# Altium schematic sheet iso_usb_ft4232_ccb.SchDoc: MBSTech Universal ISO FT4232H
size A2; DrawnBy: Andrew Carpenter; Organization: MBSTech; DocumentNumber: ISO-USB-FT4323-CCB-01; Revision: Rev00a; SheetNumber: 1; SheetTotal: 1
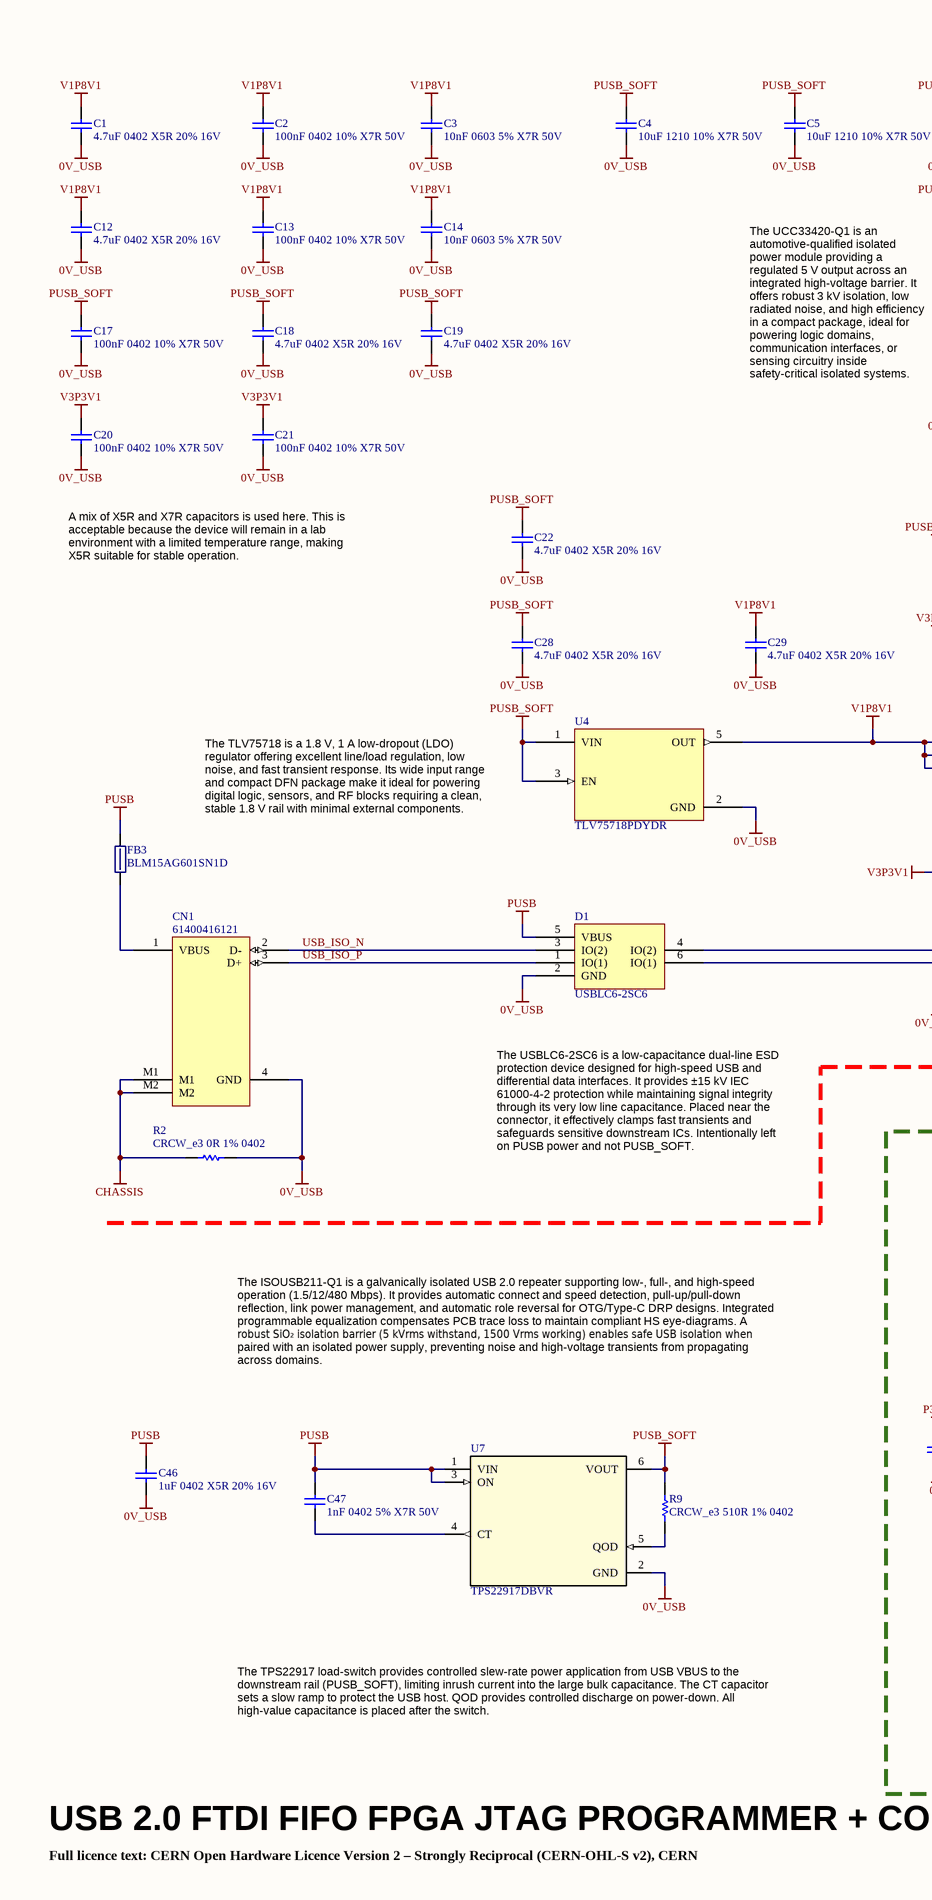
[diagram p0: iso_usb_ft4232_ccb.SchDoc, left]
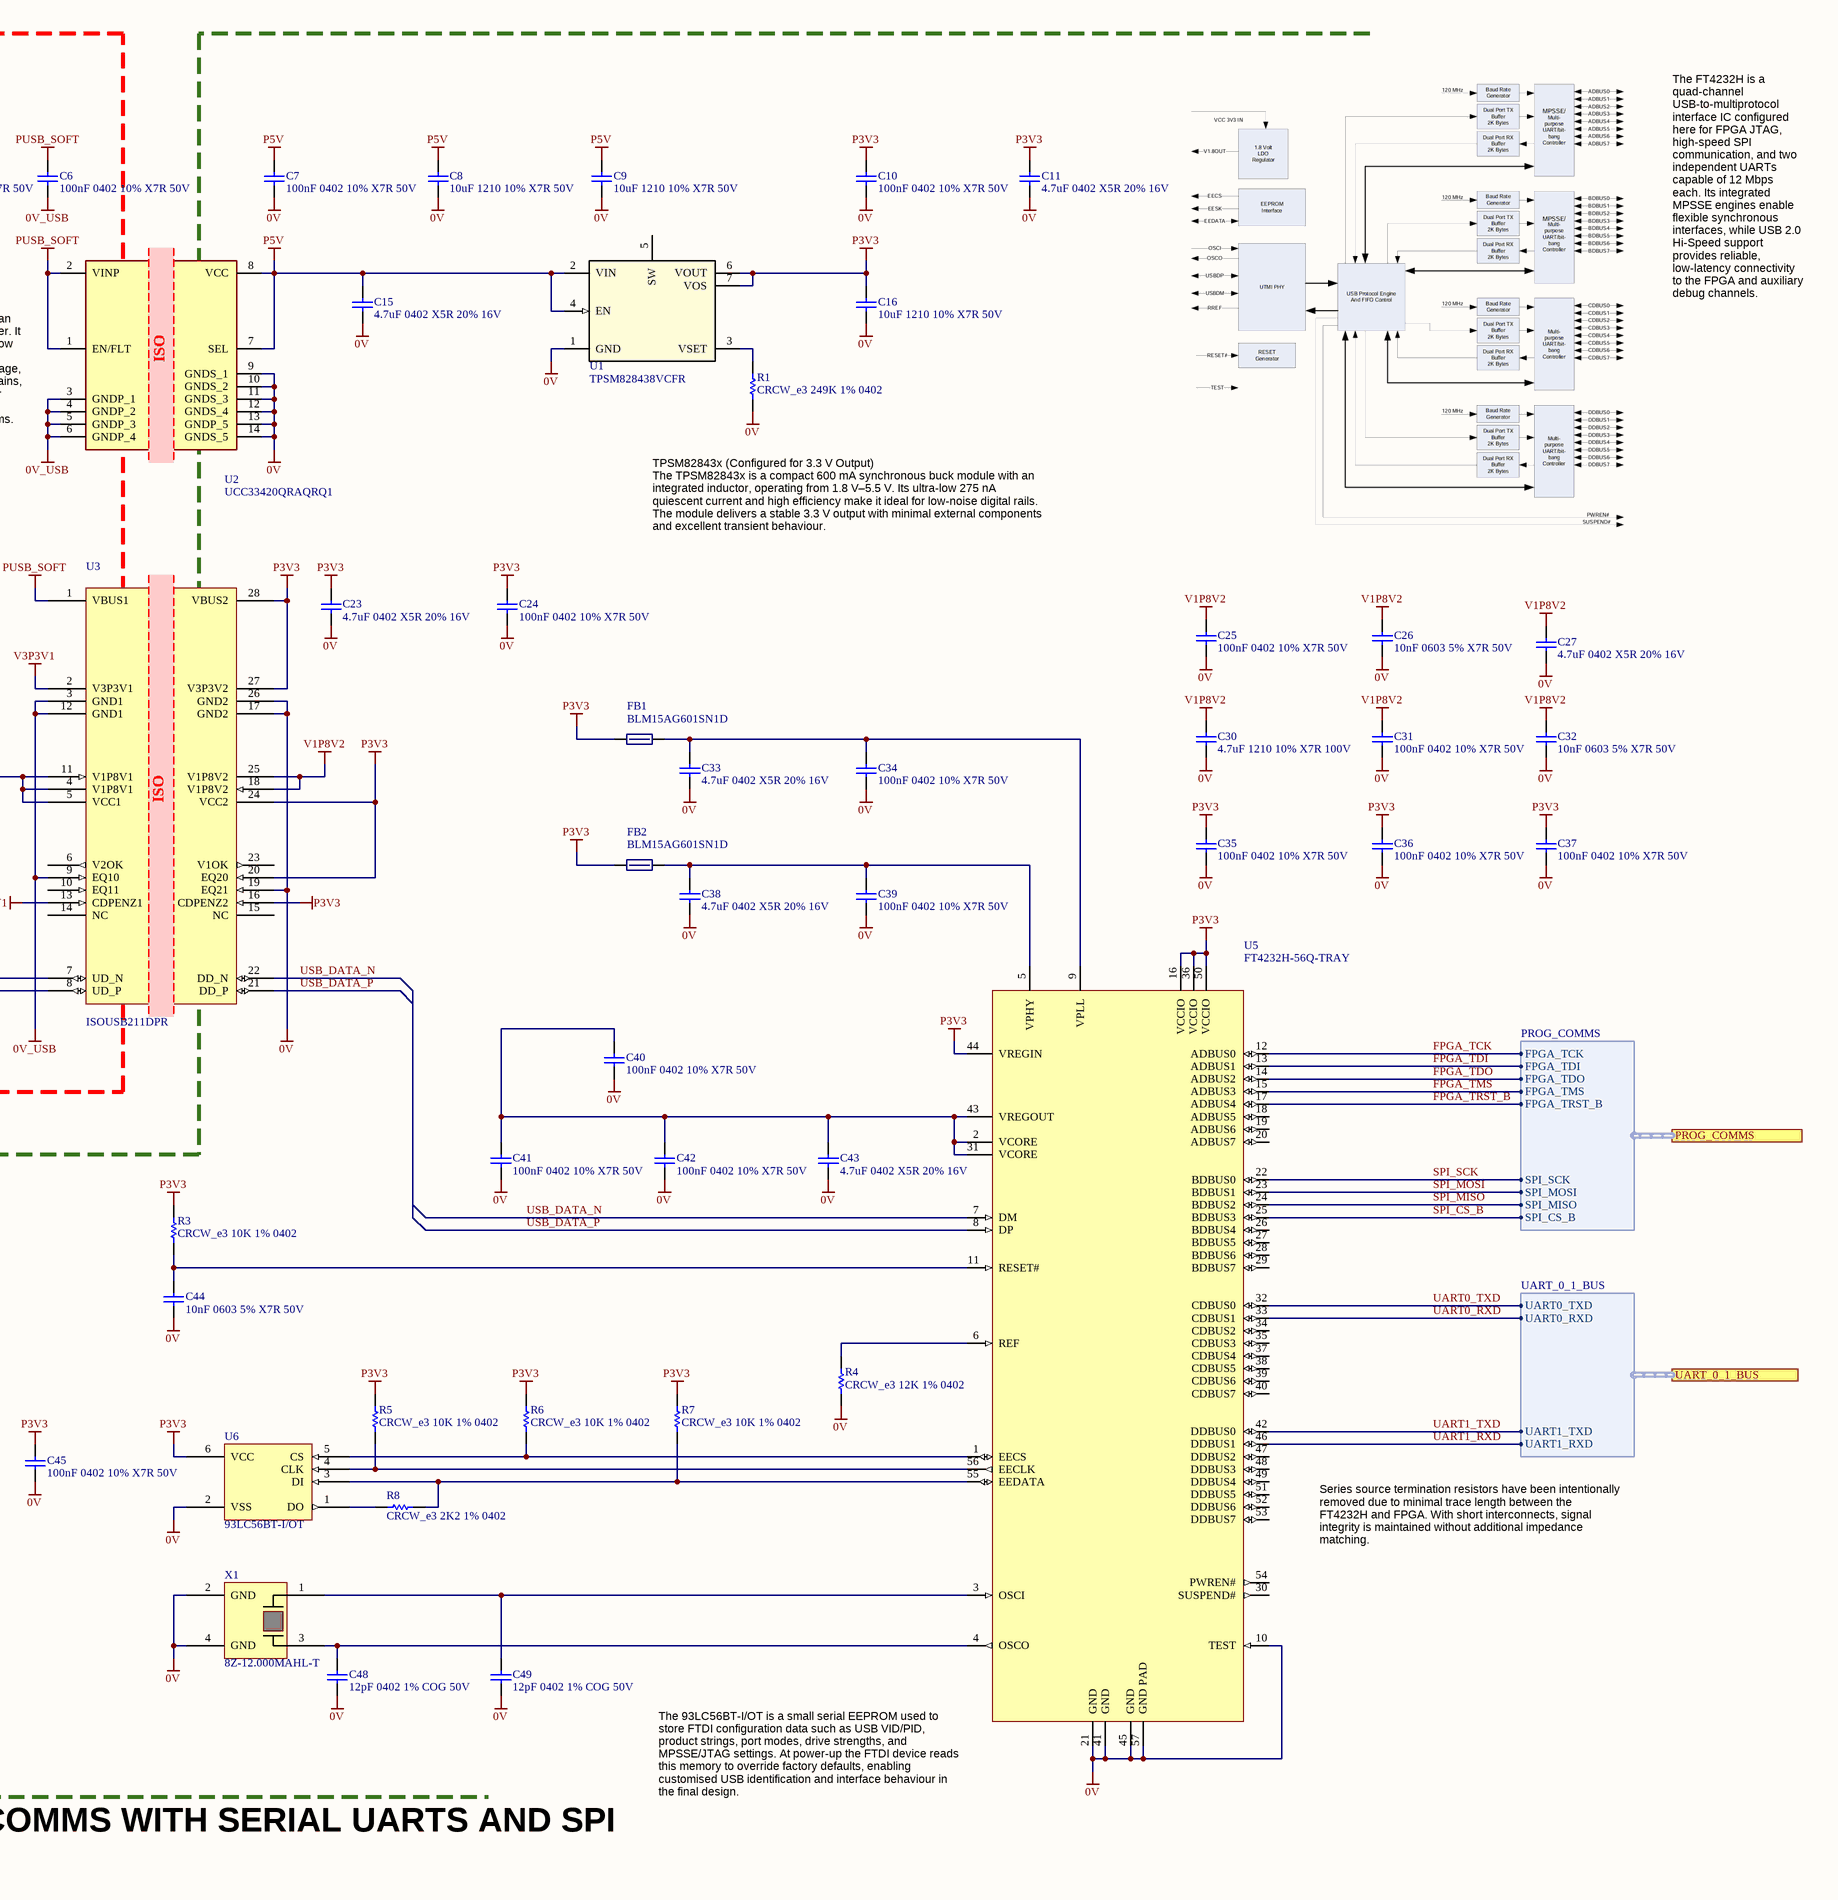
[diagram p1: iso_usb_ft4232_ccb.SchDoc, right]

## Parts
C1  4.7uF 0402 X5R 20% 16V  [CAPC100X50X56L25L-AVX0402L]
C2  100nF 0402 10% X7R 50V  [CAPC100X50X56L25L-AVX0402L]
C3  10nF 0603 5% X7R 50V  [CAPC160X81X90L35L-AVX0603L]
C4  10uF 1210 10% X7R 50V  [CAPC320X250X152L50L-AVX1210L]
C5  10uF 1210 10% X7R 50V  [CAPC320X250X152L50L-AVX1210L]
C6  100nF 0402 10% X7R 50V  [CAPC100X50X56L25L-AVX0402L]
C7  100nF 0402 10% X7R 50V  [CAPC100X50X56L25L-AVX0402L]
C8  10uF 1210 10% X7R 50V  [CAPC320X250X152L50L-AVX1210L]
C9  10uF 1210 10% X7R 50V  [CAPC320X250X152L50L-AVX1210L]
C10  100nF 0402 10% X7R 50V  [CAPC100X50X56L25L-AVX0402L]
C11  4.7uF 0402 X5R 20% 16V  [CAPC100X50X56L25L-AVX0402L]
C12  4.7uF 0402 X5R 20% 16V  [CAPC100X50X56L25L-AVX0402L]
C13  100nF 0402 10% X7R 50V  [CAPC100X50X56L25L-AVX0402L]
C14  10nF 0603 5% X7R 50V  [CAPC160X81X90L35L-AVX0603L]
C15  4.7uF 0402 X5R 20% 16V  [CAPC100X50X56L25L-AVX0402L]
C16  10uF 1210 10% X7R 50V  [CAPC320X250X152L50L-AVX1210L]
C17  100nF 0402 10% X7R 50V  [CAPC100X50X56L25L-AVX0402L]
C18  4.7uF 0402 X5R 20% 16V  [CAPC100X50X56L25L-AVX0402L]
C19  4.7uF 0402 X5R 20% 16V  [CAPC100X50X56L25L-AVX0402L]
C20  100nF 0402 10% X7R 50V  [CAPC100X50X56L25L-AVX0402L]
C21  100nF 0402 10% X7R 50V  [CAPC100X50X56L25L-AVX0402L]
C22  4.7uF 0402 X5R 20% 16V  [CAPC100X50X56L25L-AVX0402L]
C23  4.7uF 0402 X5R 20% 16V  [CAPC100X50X56L25L-AVX0402L]
C24  100nF 0402 10% X7R 50V  [CAPC100X50X56L25L-AVX0402L]
C25  100nF 0402 10% X7R 50V  [CAPC100X50X56L25L-AVX0402L]
C26  10nF 0603 5% X7R 50V  [CAPC160X81X90L35L-AVX0603L]
C27  4.7uF 0402 X5R 20% 16V  [CAPC100X50X56L25L-AVX0402L]
C28  4.7uF 0402 X5R 20% 16V  [CAPC100X50X56L25L-AVX0402L]
C29  4.7uF 0402 X5R 20% 16V  [CAPC100X50X56L25L-AVX0402L]
C30  4.7uF 1210 10% X7R 100V  [CAPC320X250X152L50L-AVX1210L]
C31  100nF 0402 10% X7R 50V  [CAPC100X50X56L25L-AVX0402L]
C32  10nF 0603 5% X7R 50V  [CAPC160X81X90L35L-AVX0603L]
C33  4.7uF 0402 X5R 20% 16V  [CAPC100X50X56L25L-AVX0402L]
C34  100nF 0402 10% X7R 50V  [CAPC100X50X56L25L-AVX0402L]
C35  100nF 0402 10% X7R 50V  [CAPC100X50X56L25L-AVX0402L]
C36  100nF 0402 10% X7R 50V  [CAPC100X50X56L25L-AVX0402L]
C37  100nF 0402 10% X7R 50V  [CAPC100X50X56L25L-AVX0402L]
C38  4.7uF 0402 X5R 20% 16V  [CAPC100X50X56L25L-AVX0402L]
C39  100nF 0402 10% X7R 50V  [CAPC100X50X56L25L-AVX0402L]
C40  100nF 0402 10% X7R 50V  [CAPC100X50X56L25L-AVX0402L]
C41  100nF 0402 10% X7R 50V  [CAPC100X50X56L25L-AVX0402L]
C42  100nF 0402 10% X7R 50V  [CAPC100X50X56L25L-AVX0402L]
C43  4.7uF 0402 X5R 20% 16V  [CAPC100X50X56L25L-AVX0402L]
C44  10nF 0603 5% X7R 50V  [CAPC160X81X90L35L-AVX0603L]
C45  100nF 0402 10% X7R 50V  [CAPC100X50X56L25L-AVX0402L]
C46  1uF 0402 X5R 20% 16V  [CAPC100X50X56L25L-AVX0402L]
C47  1nF 0402 5% X7R 50V  [CAPC100X50X56L25L-AVX0402L]
C48  12pF 0402 1% COG 50V  [CAPC100X50X56L25L-AVX0402L]
C49  12pF 0402 1% COG 50V  [CAPC100X50X56L25L-AVX0402L]
CN1  61400416121  [61400416121]
D1  USBLC6-2SC6  [SOT23-6L]
FB1  BLM15AG601SN1D  [BEADC100X50X55L25-FB0402L]
FB2  BLM15AG601SN1D  [BEADC100X50X55L25-FB0402L]
FB3  BLM15AG601SN1D  [BEADC100X50X55L25-FB0402L]
R1  CRCW_e3 249K 1% 0402  [RESC100X50X40L25-CRCW0402L]
R2  CRCW_e3 0R 1% 0402  [RESC100X50X40L25-CRCW0402L]
R3  CRCW_e3 10K 1% 0402  [RESC100X50X40L25-CRCW0402L]
R4  CRCW_e3 12K 1% 0402  [RESC100X50X40L25-CRCW0402L]
R5  CRCW_e3 10K 1% 0402  [RESC100X50X40L25-CRCW0402L]
R6  CRCW_e3 10K 1% 0402  [RESC100X50X40L25-CRCW0402L]
R7  CRCW_e3 10K 1% 0402  [RESC100X50X40L25-CRCW0402L]
R8  CRCW_e3 2K2 1% 0402  [RESC100X50X40L25-CRCW0402L]
R9  CRCW_e3 510R 1% 0402  [RESC100X50X40L25-CRCW0402L]
U1  TPSM828438VCFR  [VCF0007A-MFG]
U2  UCC33420QRAQRQ1  [UCC33020QRAQRQ1]
U3  ISOUSB211DPR  [DP0028A-TI]
U4  TLV75718PDYDR  [SOT23-5P95_280X145L45X35L-AP2127-SOT23-5L]
U5  FT4232H-56Q-TRAY  [QFN57P50_800X800X100L40X25T610N-FTDIQFN56N]
U6  93LC56BT-I/OT  [SOT23-6P95_280X145L45X37N]
U7  TPS22917DBVR  [SOT23-6P95_280X100L40X37-LM5050-1]
X1  8Z-12.000MAHL-T  [OSCCC250X200X55L65X80-TXC-8ZL]

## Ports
PROG_COMMS (harness PROG_COMMS), UART_0_1_BUS (harness UART_0_1_BUS)

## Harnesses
UART_0_1_BUS: UART0_TXD, UART0_RXD, UART1_TXD, UART1_RXD
PROG_COMMS: FPGA_TCK, FPGA_TDI, FPGA_TDO, FPGA_TMS, FPGA_TRST_B, SPI_SCK, SPI_MOSI, SPI_MISO, SPI_CS_B

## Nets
0V: C7.1 C8.1 C9.1 C10.1 C11.1 C15.1 C16.1 C23.1 C24.1 C25.1 C26.1 C27.1 C30.1 C31.1 C32.1 C33.1 C34.1 C35.1 C36.1 C37.1 C38.1 C39.1 C40.1 C41.1 C42.1 C43.1 C44.1 C45.1 C48.1 C49.2 R1.1 R4.1 U1.1(GND) U2.9(GNDS_1) U2.10(GNDS_2) U2.11(GNDS_3) U2.12(GNDS_4) U2.13(GNDP_5) U2.14(GNDS_5) U3.17(GND2) U3.19(EQ21) U3.26(GND2) U5.10(TEST) U5.21(GND) U5.41(GND) U5.45(GND) U5.57(GND_PAD) U6.2(VSS) X1.2(GND) X1.4(GND)
0V_USB: C1.1 C2.1 C3.1 C4.1 C5.1 C6.1 C12.1 C13.1 C14.1 C17.1 C18.1 C19.1 C20.1 C21.1 C22.1 C28.1 C29.1 C46.1 CN1.4(GND) D1.2(GND) R2.2 U2.3(GNDP_1) U2.4(GNDP_2) U2.5(GNDP_3) U2.6(GNDP_4) U3.3(GND1) U3.9(EQ10) U3.12(GND1) U4.2(GND) U7.2(GND)
CHASSIS: CN1.M1 CN1.M2 R2.1
P3V3: C10.2 C11.2 C16.2 C23.2 C24.2 C35.2 C36.2 C37.2 C45.2 FB1.1 FB2.1 R3.1 R5.2 R6.2 R7.2 U1.6(VOUT) U1.7(VOS) U3.16(CDPENZ2) U3.20(EQ20) U3.24(VCC2) U3.27(V3P3V2) U3.28(VBUS2) U5.16(VCCIO) U5.36(VCCIO) U5.44(VREGIN) U5.50(VCCIO) U6.6(VCC)
P5V: C7.2 C8.2 C9.2 C15.2 U1.2(VIN) U1.4(EN) U2.7(SEL) U2.8(VCC)
PUSB: C46.2 C47.2 D1.5(VBUS) FB3.2 U7.1(VIN) U7.3(ON)
PUSB_SOFT: C4.2 C5.2 C6.2 C17.2 C18.2 C19.2 C22.2 C28.2 R9.2 U2.1(EN/FLT) U2.2(VINP) U3.1(VBUS1) U4.1(VIN) U4.3(EN) U7.6(VOUT)
V1P8V1: C1.2 C2.2 C3.2 C12.2 C13.2 C14.2 C29.2 U3.4(V1P8V1) U3.5(VCC1) U3.11(V1P8V1) U4.5(OUT)
V1P8V2: C25.2 C26.2 C27.2 C30.2 C31.2 C32.2 U3.18(V1P8V2) U3.25(V1P8V2)
V3P3V1: C20.2 C21.2 U3.2(V3P3V1) U3.13(CDPENZ1)
FPGA_TCK: U5.12(ADBUS0) ; port PROG_COMMS.FPGA_TCK
FPGA_TDI: U5.13(ADBUS1) ; port PROG_COMMS.FPGA_TDI
FPGA_TDO: U5.14(ADBUS2) ; port PROG_COMMS.FPGA_TDO
FPGA_TMS: U5.15(ADBUS3) ; port PROG_COMMS.FPGA_TMS
FPGA_TRST_B: U5.17(ADBUS4) ; port PROG_COMMS.FPGA_TRST_B
SPI_CS_B: U5.25(BDBUS3) ; port PROG_COMMS.SPI_CS_B
SPI_MISO: U5.24(BDBUS2) ; port PROG_COMMS.SPI_MISO
SPI_MOSI: U5.23(BDBUS1) ; port PROG_COMMS.SPI_MOSI
SPI_SCK: U5.22(BDBUS0) ; port PROG_COMMS.SPI_SCK
UART0_RXD: U5.33(CDBUS1) ; port UART_0_1_BUS.UART0_RXD
UART0_TXD: U5.32(CDBUS0) ; port UART_0_1_BUS.UART0_TXD
UART1_RXD: U5.46(DDBUS1) ; port UART_0_1_BUS.UART1_RXD
UART1_TXD: U5.42(DDBUS0) ; port UART_0_1_BUS.UART1_TXD
USB_DATA_N: U3.22(DD_N) U5.7(DM)
USB_DATA_P: U3.21(DD_P) U5.8(DP)
USB_ISO_N: CN1.2(D-) D1.3(IO(2))
USB_ISO_P: CN1.3(D+) D1.1(IO(1))
NetC33_2: C33.2 C34.2 FB1.2 U5.9(VPLL)
NetC38_2: C38.2 C39.2 FB2.2 U5.5(VPHY)
NetC40_2: C40.2 C41.2 C42.2 C43.2 U5.2(VCORE) U5.31(VCORE) U5.43(VREGOUT)
NetC44_2: C44.2 R3.2 U5.11(RESET#)
NetC47_1: C47.1 U7.4(CT)
NetC48_2: C48.2 U5.4(OSCO) X1.3
NetC49_1: C49.1 U5.3(OSCI) X1.1
NetCN1_1: CN1.1(VBUS) FB3.1
NetD1_4: D1.4(IO(2)) U3.7(UD_N)
NetD1_6: D1.6(IO(1)) U3.8(UD_P)
NetR1_2: R1.2 U1.3(VSET)
NetR4_2: R4.2 U5.6(REF)
NetR5_1: R5.1 U5.56(EECLK) U6.4(CLK)
NetR6_1: R6.1 U5.1(EECS) U6.5(CS)
NetR7_1: R7.1 R8.2 U5.55(EEDATA) U6.3(DI)
NetR8_1: R8.1 U6.1(DO)
NetR9_1: R9.1 U7.5(QOD)

Not connected (* = marked no-connect by the designer): U1 5(SW); U3 6(V2OK) 10(EQ11) 14(NC) 15(NC) 23(V1OK); U5 18(ADBUS5) 19(ADBUS6) 20(ADBUS7) 26(BDBUS4) 27(BDBUS5) 28(BDBUS6) 29(BDBUS7) 30(SUSPEND#) 34(CDBUS2) 35(CDBUS3) 37(CDBUS4) 38(CDBUS5) 39(CDBUS6) 40(CDBUS7) 47(DDBUS2) 48(DDBUS3) 49(DDBUS4) 51(DDBUS5) 52(DDBUS6) 53(DDBUS7) 54(PWREN#)

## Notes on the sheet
- The FT4232H is a quad-channel USB-to-multiprotocol interface IC configured here for FPGA JTAG, high-speed SPI communication, and two independent UARTs capable of 12 Mbps each. Its integrated MPSSE engines enable flexible synchronous interfaces, while USB 2.0 Hi-Speed support provides reliable, low-latency connectivity to the FPGA and auxiliary debug channels.
- The UCC33420-Q1 is an automotive-qualified isolated power module providing a regulated 5 V output across an integrated high-voltage barrier. It offers robust 3 kV isolation, low radiated noise, and high efficiency in a compact package, ideal for powering logic domains, communication interfaces, or sensing circuitry inside safety-critical isolated systems.
- TPSM82843x (Configured for 3.3 V Output)
  The TPSM82843x is a compact 600 mA synchronous buck module with an integrated inductor, operating from 1.8 V–5.5 V. Its ultra-low 275 nA quiescent current and high efficiency make it ideal for low-noise digital rails. The module delivers a stable 3.3 V output with minimal external components and excellent transient behaviour.
- A mix of X5R and X7R capacitors is used here. This is acceptable because the device will remain in a lab environment with a limited temperature range, making X5R suitable for stable operation.
- The TLV75718 is a 1.8 V, 1 A low-dropout (LDO) regulator offering excellent line/load regulation, low noise, and fast transient response. Its wide input range and compact DFN package make it ideal for powering digital logic, sensors, and RF blocks requiring a clean, stable 1.8 V rail with minimal external components.
- The USBLC6-2SC6 is a low-capacitance dual-line ESD protection device designed for high-speed USB and differential data interfaces. It provides ±15 kV IEC 61000-4-2 protection while maintaining signal integrity through its very low line capacitance. Placed near the connector, it effectively clamps fast transients and safeguards sensitive downstream ICs. Intentionally left on PUSB power and not PUSB_SOFT.
- The ISOUSB211-Q1 is a galvanically isolated USB 2.0 repeater supporting low-, full-, and high-speed operation (1.5/12/480 Mbps). It provides automatic connect and speed detection, pull-up/pull-down reflection, link power management, and automatic role reversal for OTG/Type-C DRP designs. Integrated programmable equalization compensates PCB trace loss to maintain compliant HS eye-diagrams. A robust SiO₂ isolation barrier (5 kVrms withstand, 1500 Vrms working) enables safe USB isolation when paired with an isolated power supply, preventing noise and high-voltage transients from propagating across domains.
- Series source termination resistors have been intentionally removed due to minimal trace length between the FT4232H and FPGA. With short interconnects, signal integrity is maintained without additional impedance matching.
- The TPS22917 load-switch provides controlled slew-rate power application from USB VBUS to the downstream rail (PUSB_SOFT), limiting inrush current into the large bulk capacitance. The CT capacitor sets a slow ramp to protect the USB host. QOD provides controlled discharge on power-down. All high-value capacitance is placed after the switch.
- USB 2.0 FTDI FIFO FPGA JTAG PROGRAMMER + COMMS WITH SERIAL UARTS AND SPI
- Full licence text: CERN Open Hardware Licence Version 2 – Strongly Reciprocal (CERN-OHL-S v2), CERN
- (near U5) The 93LC56BT-I/OT is a small serial EEPROM used to store FTDI configuration data such as USB VID/PID, product strings, port modes, drive strengths, and MPSSE/JTAG settings. At power-up the FTDI device reads this memory to override factory defaults, enabling customised USB identification and interface behaviour in the final design.

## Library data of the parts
C1 C11 C12 C15 C18 C19 C22 C23 C27-C29 C33 C38 C43 = 0402YD475MAT2A: Multilayer Ceramic Capacitors MLCC - SMD/SMT 16V 4.7uF X5R 0402; Manufacturer: AVX
C2 C6 C7 C10 C13 C17 C20 C21 C24 C25 C31 C34-C37 C39-C42 C45 = 04025C104KAT2A: Multilayer Ceramic Capacitors MLCC - SMD/SMT 50V .1uF X7R 0402 10%TOL; Manufacturer: AVX
C3 C14 C26 C32 C44 = 06035C103J4Z2A: Multilayer Ceramic Capacitors MLCC - SMD/SMT 50V .01uF X7R 0603 5% TOL; Manufacturer: AVX
C4 C5 C8 C9 C16 = 12105C106K4Z2A: Multilayer Ceramic Capacitors MLCC - SMD/SMT 50V 10uF X7R 1210 10%TOL AEC-Q200; Manufacturer: AVX
C30 = 12101C475K4Z2A: Multilayer Ceramic Capacitors MLCC - SMD/SMT 100V 4.7uF X7R 1210 10% Tol AEC-Q200; Manufacturer: AVX
C46 = 0402YD105MAT2A: Multilayer Ceramic Capacitors MLCC - SMD/SMT 16V 1uF X5R 0402; Manufacturer: AVX
C47 = 04025C102J4T2A: Multilayer Ceramic Capacitors MLCC - SMD/SMT 50V 1000pF X7R 0402 Tol 5% AEC-Q200; Manufacturer: AVX
C48 C49 = 04025A120F4T2A: Multilayer Ceramic Capacitors MLCC - SMD/SMT 50V 12pF C0G 0402 1% AEC-Q200; Manufacturer: AVX
CN1 = 61400416121: USB Connectors WR-COM Type B 4Pin Horztl Female; Manufacturer: Wurth
D1 = USBLC6-2SC6: ESD Suppressors / TVS Diodes ESD Protection Low Cap; Manufacturer: ST Microelectronics
FB1-FB3 = BLM15AG601SN1D: MURATA  BLM15AG601SN1D  FERRITE, BEAD, 0402, 0.6OHM, 0.3A
R1 = CRCW0402249KFKED: Thick Film Resistors - SMD 249K ohm 1%; Manufacturer: VISHAY
R2 = CRCW04020000Z0ED: Thick Film Resistors - SMD 0 ohm 1%; Manufacturer: VISHAY
R3 R5-R7 = CRCW040210K0FKED: Thick Film Resistors - SMD 10K ohm 1%; Manufacturer: VISHAY
R4 = CRCW040212K0FKED: Thick Film Resistors - SMD 12K ohm 1%; Manufacturer: VISHAY
R8 = CRCW04022K20FKED: Thick Film Resistors - SMD 2K2 ohm 1%; Manufacturer: VISHAY
R9 = CRCW0402510RFKED: Thick Film Resistors - SMD 510R ohm 1%; Manufacturer: VISHAY
U1 = TPSM828438VCFR: Switching Voltage Regulators 275nA IQ 0.4V to 3. 6V selectable VOUT; Manufacturer: Texas Instruments
U2 = UCC33420QRAQRQ1: Power Management Modules Automotive, 5V/5V 1.5W 3kVrms isolated DC-DC module with integrated transformer; Manufacturer: Texas Instruments
U3 = ISOUSB211DPR: ISOUSB211-Q1 High/Full/Low Speed Isolated USB Repeater; Manufacturer: Texas Instruments
U4 = TLV75718PDYDR: LDO Voltage Regulators 1.8V and 1A low-IQ high-accuracy low-dropout; Manufacturer: Texas Instruments
U5 = FT4232H-56Q-TRAY: USB Interface IC Quad 480Mbs 4 UART USB 2.0 12Mbit; Manufacturer: FTDI
U6 = 93LC56BT-I/OT: MICROCHIP - 93LC56BT-I/OT - IC, EEPROM, 2KBIT, SERIAL, 3MHZ SOT-23-6
U7 = TPS22917DBVR: Power Switch ICs - Power Distribution 5.5-V 2-A 80-mohm 10-nA leakage load A 595-TPS22917DBVT; Manufacturer: Texas Instruments; Manufacturer Part Number: LM5050Q0MKX-1/NOPB
X1 = 8Z-12.000MAHL-T: Crystals 12MHz 30ppm 22pF -40C +85C  2.5mm X 2mm; Manufacturer: TXC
